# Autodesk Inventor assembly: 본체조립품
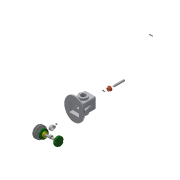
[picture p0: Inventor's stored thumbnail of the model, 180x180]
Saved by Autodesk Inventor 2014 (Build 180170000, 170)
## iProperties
Created: 2017-07
Part Number: 본체조립품
Document SubType Name: Assembly
Designer: user
Author: user
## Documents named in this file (16)
- C:\Users\user\Desktop\470707V1003\본체조립품.iam
- C:\Users\user\Desktop\470707V1003\V벨트풀리.ipt
- C:\Users\user\Desktop\470707V1003\고정핀 1.2 x  8.ipt
- C:\Users\user\Desktop\470707V1003\뒤커버.ipt
- C:\Users\user\Desktop\470707V1003\링크.ipt
- C:\Users\user\Desktop\470707V1003\멈춤나사 M3x8.ipt
- C:\Users\user\Desktop\470707V1003\베어링 12 x 32 x 10.ipt
- C:\Users\user\Desktop\470707V1003\본체.ipt
- C:\Users\user\Desktop\470707V1003\볼트 M4 x 12.ipt
- C:\Users\user\Desktop\470707V1003\부시.ipt
- C:\Users\user\Desktop\470707V1003\슬라이드.ipt
- C:\Users\user\Desktop\470707V1003\앞커버.ipt
- C:\Users\user\Desktop\470707V1003\오일실 12 25 7.ipt
- C:\Users\user\Desktop\470707V1003\키 4 x 4 x 10.ipt
- C:\Users\user\Desktop\470707V1003\편심축.ipt
- C:\Users\user\Desktop\470707V1003\핀 5 x 18.ipt
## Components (3 placed, 3 different names)
1. V벨트풀리:1 — Insert:8
2. 고정핀 1.2 x  8:1
3. 핀 5 x 18:1
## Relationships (1: Insert 1)
- Insert:8: V벨트풀리:1
